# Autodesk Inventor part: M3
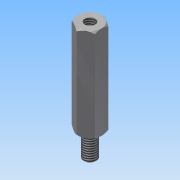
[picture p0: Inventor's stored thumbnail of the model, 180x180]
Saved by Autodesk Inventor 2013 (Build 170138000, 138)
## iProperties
Created: 2012-08
Part Number: M3
Material: Stahl
Document SubType Name: Modeling
Designer: rYan
Density: 7.85 g/cm^3
Mass: 4.57996 g
Surface Area: 5.77966 cm^2
Volume: 0.583435 cm^3
Author: rYan
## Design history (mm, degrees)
derived "Abstandsbolzen Typ B.ipt"
feature "Volumenkörper1::Abstandsbolzen Typ B.ipt"
tag "Bezeichnung1"
node "Volumenkörper1"
other parameters: "SW" = 5.5, "L" = 22, "d2" = 0, "l_" = 7, "d9" = 118 deg, "GA_" = 3, "A_" = 6, "d13" = 0, "d17" = 0.25, "d20" = 45 deg
